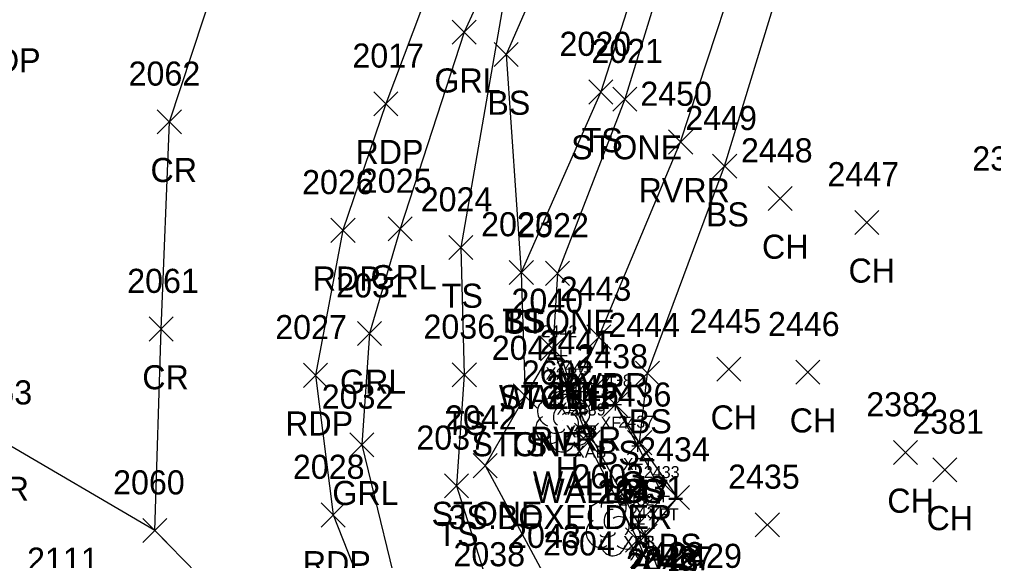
# Model space of a CAD drawing. Extents: x 1459992 to 1461532, y 647785 to 648535.
# Drawn here: x 1461256.6 to 1461337.5, y 648237.3 to 648282.2 of the extents above; entities that cross this region are included whole.
import ezdxf

# ---------------------------------------------------------------- set-up
doc = ezdxf.new("R2010")
doc.units = 0
for name, color, linetype in [('B_A', 7, 'Continuous'), ('B_I', 7, 'Continuous'), ('B_TIC', 7, 'Continuous'), ('BFT', 7, 'Continuous'), ('BSUBM', 7, 'Continuous'), ('L_A', 7, 'Continuous'), ('L_C', 7, 'Continuous'), ('L_I', 7, 'Continuous'), ('L_TIC', 7, 'Continuous'), ('LASF', 7, 'Continuous'), ('LAWE', 7, 'Continuous'), ('LELB', 7, 'Continuous'), ('LTD', 7, 'Continuous'), ('LW', 7, 'Continuous'), ('P_A', 7, 'Continuous'), ('P_I', 7, 'Continuous'), ('P_TIC', 7, 'Continuous'), ('PET', 7, 'Continuous'), ('PRC', 7, 'Continuous'), ('R_A', 7, 'Continuous'), ('R_I', 7, 'Continuous'), ('R_TIC', 7, 'Continuous'), ('RGR', 7, 'Continuous')]:
    doc.layers.add(name, color=color, linetype=linetype)

msp = doc.modelspace()

# ---------------------------------------------------------------- linework, layer by layer
at = {"layer": 'B_TIC'}
for p, q in [((1461301.592, 648254.329), (1461301.668, 648254.329)), ((1461302.498, 648251.414), (1461302.573, 648251.414)), ((1461306.117, 648250.248), (1461306.193, 648250.248)), ((1461303.233, 648249.536), (1461303.309, 648249.536)), ((1461303.233, 648249.536), (1461303.309, 648249.536)), ((1461303.947, 648247.839), (1461304.022, 648247.839)), ((1461307.973, 648246.826), (1461308.049, 648246.826)), ((1461310.088, 648242.646), (1461310.164, 648242.646)), ((1461308.01, 648240.352), (1461308.085, 648240.352)), ((1461308.01, 648240.352), (1461308.085, 648240.352)), ((1461308.563, 648239.319), (1461308.638, 648239.319))]:
    msp.add_line(p, q, dxfattribs=at)
for points in [[(1461301.589, 648253.829), (1461301.589, 648254.829)], [(1461301.089, 648254.329), (1461302.089, 648254.329)], [(1461301.994, 648251.414), (1461302.994, 648251.414)], [(1461302.494, 648250.914), (1461302.494, 648251.914)], [(1461306.114, 648249.748), (1461306.114, 648250.748)], [(1461303.23, 648249.036), (1461303.23, 648250.036)], [(1461303.23, 648249.036), (1461303.23, 648250.036)], [(1461305.614, 648250.248), (1461306.614, 648250.248)], [(1461302.73, 648249.536), (1461303.73, 648249.536)], [(1461302.73, 648249.536), (1461303.73, 648249.536)], [(1461303.943, 648247.339), (1461303.943, 648248.339)], [(1461303.443, 648247.839), (1461304.443, 648247.839)], [(1461307.47, 648246.826), (1461308.47, 648246.826)], [(1461307.97, 648246.326), (1461307.97, 648247.326)], [(1461309.585, 648242.646), (1461310.585, 648242.646)], [(1461310.085, 648242.146), (1461310.085, 648243.146)], [(1461307.506, 648240.352), (1461308.506, 648240.352)], [(1461307.506, 648240.352), (1461308.506, 648240.352)], [(1461308.006, 648239.852), (1461308.006, 648240.852)], [(1461308.006, 648239.852), (1461308.006, 648240.852)], [(1461308.059, 648239.319), (1461309.059, 648239.319)], [(1461308.559, 648238.819), (1461308.559, 648239.819)]]:
    msp.add_lwpolyline(points, dxfattribs=at)
at = {"layer": 'BFT'}
msp.add_lwpolyline([(1461308.006, 648240.352), (1461310.085, 648242.646), (1461307.97, 648246.826), (1461306.114, 648250.248), (1461303.23, 648249.536)], dxfattribs=at)
at = {"layer": 'BSUBM'}
msp.add_lwpolyline([(1461289.479, 648204.615), (1461290.611, 648203.988), (1461292.337, 648203.444), (1461295.791, 648207.872), (1461298.63, 648210.737), (1461303.235, 648215.695), (1461306.926, 648219.818), (1461308.297, 648222.092), (1461310.762, 648233.32), (1461310.733, 648233.836), (1461308.559, 648239.319), (1461308.006, 648240.352), (1461303.943, 648247.839), (1461303.23, 648249.536), (1461302.494, 648251.414), (1461301.589, 648254.329)], dxfattribs=at)
at = {"layer": 'L_TIC'}
for points in [[(1461296.024, 648278.303), (1461298.024, 648280.303)], [(1461298.024, 648278.303), (1461296.024, 648280.303)], [(1461303.882, 648275.195), (1461305.882, 648277.195)], [(1461305.882, 648275.195), (1461303.882, 648277.195)], [(1461305.874, 648274.606), (1461307.874, 648276.606)], [(1461307.874, 648274.606), (1461305.874, 648276.606)], [(1461310.515, 648271.047), (1461312.515, 648273.047)], [(1461312.515, 648271.047), (1461310.515, 648273.047)], [(1461314.171, 648269.035), (1461316.171, 648271.035)], [(1461316.171, 648269.035), (1461314.171, 648271.035)], [(1461318.786, 648266.354), (1461320.786, 648268.354)], [(1461320.786, 648266.354), (1461318.786, 648268.354)], [(1461325.969, 648264.372), (1461327.969, 648266.372)], [(1461327.969, 648264.372), (1461325.969, 648266.372)], [(1461292.267, 648262.285), (1461294.267, 648264.285)], [(1461294.267, 648262.285), (1461292.267, 648264.285)], [(1461297.284, 648260.218), (1461299.284, 648262.218)], [(1461299.284, 648260.218), (1461297.284, 648262.218)], [(1461297.284, 648260.218), (1461299.284, 648262.218)], [(1461299.284, 648260.218), (1461297.284, 648262.218)], [(1461300.288, 648260.14), (1461302.288, 648262.14)], [(1461302.288, 648260.14), (1461300.288, 648262.14)], [(1461303.732, 648254.86), (1461305.732, 648256.86)], [(1461305.732, 648254.86), (1461303.732, 648256.86)], [(1461299.891, 648253.869), (1461301.891, 648255.869)], [(1461301.891, 648253.869), (1461299.891, 648255.869)], [(1461299.891, 648253.869), (1461301.891, 648255.869)], [(1461301.891, 648253.869), (1461299.891, 648255.869)], [(1461307.77, 648251.863), (1461309.77, 648253.863)], [(1461309.77, 648251.863), (1461307.77, 648253.863)], [(1461314.515, 648252.183), (1461316.515, 648254.183)], [(1461316.515, 648252.183), (1461314.515, 648254.183)], [(1461321.086, 648251.933), (1461323.086, 648253.933)], [(1461323.086, 648251.933), (1461321.086, 648253.933)], [(1461292.552, 648251.72), (1461294.552, 648253.72)], [(1461294.552, 648251.72), (1461292.552, 648253.72)], [(1461301.494, 648250.414), (1461303.494, 648252.414)], [(1461303.494, 648250.414), (1461301.494, 648252.414)], [(1461297.603, 648249.96), (1461299.603, 648251.96)], [(1461299.603, 648249.96), (1461297.603, 648251.96)], [(1461297.603, 648249.96), (1461299.603, 648251.96)], [(1461299.603, 648249.96), (1461297.603, 648251.96)], [(1461305.114, 648249.248), (1461307.114, 648251.248)], [(1461307.114, 648249.248), (1461305.114, 648251.248)], [(1461302.696, 648246.711), (1461304.696, 648248.711)], [(1461304.696, 648246.711), (1461302.696, 648248.711)], [(1461302.821, 648246.088), (1461304.821, 648248.088)], [(1461304.821, 648246.088), (1461302.821, 648248.088)], [(1461307.112, 648246.085), (1461309.112, 648248.085)], [(1461309.112, 648246.085), (1461307.112, 648248.085)], [(1461307.112, 648246.085), (1461309.112, 648248.085)], [(1461309.112, 648246.085), (1461307.112, 648248.085)], [(1461329.192, 648245.273), (1461331.192, 648247.273)], [(1461331.192, 648245.273), (1461329.192, 648247.273)], [(1461294.289, 648244.182), (1461296.289, 648246.182)], [(1461296.289, 648244.182), (1461294.289, 648246.182)], [(1461332.45, 648243.824), (1461334.45, 648245.824)], [(1461334.45, 648243.824), (1461332.45, 648245.824)], [(1461291.905, 648242.507), (1461293.905, 648244.507)], [(1461293.905, 648242.507), (1461291.905, 648244.507)], [(1461310.248, 648241.529), (1461312.248, 648243.529)], [(1461312.248, 648241.529), (1461310.248, 648243.529)], [(1461317.719, 648239.265), (1461319.719, 648241.265)], [(1461319.719, 648239.265), (1461317.719, 648241.265)], [(1461307.559, 648238.319), (1461309.559, 648240.319)], [(1461309.559, 648238.319), (1461307.559, 648240.319)], [(1461306.944, 648238.012), (1461308.944, 648240.012)], [(1461308.944, 648238.012), (1461306.944, 648240.012)]]:
    msp.add_lwpolyline(points, dxfattribs=at)
at = {"layer": 'LASF'}
msp.add_lwpolyline([(1461385.213, 648380.492), (1461366.248, 648363.55), (1461348.098, 648349.519), (1461330.912, 648328.279), (1461323.073, 648320.206), (1461313.493, 648297.123), (1461306.874, 648275.606), (1461301.288, 648261.14), (1461300.891, 648254.869), (1461298.603, 648250.96), (1461295.289, 648245.182), (1461300.607, 648235.351), (1461302.655, 648226.754), (1461299.855, 648225.177), (1461298.501, 648223.598), (1461297.241, 648222.361)], dxfattribs=at)
at = {"layer": 'LAWE'}
msp.add_lwpolyline([(1461302.494, 648251.414), (1461304.732, 648255.86), (1461311.515, 648272.047), (1461318.184, 648292.347), (1461320.876, 648299.253), (1461325.88, 648305.325), (1461332.947, 648314.572), (1461346.563, 648331.413), (1461356.783, 648344.505), (1461369.936, 648357.821), (1461389.241, 648367.573), (1461411.269, 648373.546), (1461437.484, 648371.916), (1461454.448, 648377.931), (1461478.943, 648382.173)], dxfattribs=at)
at = {"layer": 'LELB'}
for points in [[(1461437.888, 648410.488), (1461418.935, 648407.67), (1461409.615, 648403.832), (1461397.123, 648398.784), (1461381.61, 648386.31), (1461361.675, 648369.148), (1461343.966, 648353.542), (1461325.103, 648333.829), (1461318.696, 648322.255), (1461308.654, 648307.17), (1461301.589, 648300.067), (1461298.1, 648291.151), (1461293.267, 648263.285), (1461293.552, 648252.72), (1461292.905, 648243.507), (1461295.985, 648233.828), (1461296.733, 648225.477), (1461296.732, 648222.487)], [(1461409.615, 648403.832), (1461399.481, 648396.087), (1461384.513, 648382.595), (1461363.674, 648367.201), (1461346.459, 648351.009), (1461329.681, 648330.054), (1461321.263, 648319.556), (1461311.802, 648297.779), (1461304.882, 648276.195), (1461298.284, 648261.218), (1461298.603, 648250.96)], [(1461308.559, 648239.319), (1461311.248, 648242.529), (1461308.112, 648247.085), (1461308.77, 648252.863), (1461315.171, 648270.035), (1461321.583, 648291.019), (1461329.024, 648302.011), (1461334.847, 648312.35), (1461349.259, 648326.907), (1461358.54, 648342.564), (1461371.773, 648355.493), (1461390.676, 648365.061), (1461413.445, 648369.696), (1461437.721, 648367.905), (1461455.543, 648374.902), (1461479.25, 648378.908)], [(1461322.757, 648336.157), (1461311.114, 648316.428), (1461308.654, 648307.17), (1461305.395, 648298.419), (1461297.024, 648279.303), (1461298.284, 648261.218)], [(1461308.112, 648247.085), (1461306.114, 648250.248)]]:
    msp.add_lwpolyline(points, dxfattribs=at)
at = {"layer": 'LTD'}
for p, q in [((1461301.713, 648248.911), (1461301.713, 648248.911)), ((1461301.713, 648248.911), (1461301.713, 648248.911)), ((1461305.912, 648240.29), (1461305.912, 648240.29)), ((1461305.912, 648240.29), (1461305.912, 648240.29))]:
    msp.add_line(p, q, dxfattribs=at)
for centre in [(1461301.76, 648250.345), (1461305.959, 648241.724)]:
    msp.add_arc(centre, 1.047, 335.52715, 180.95627, dxfattribs=at)
for centre, major_axis, ratio, start_param, end_param in [((1461300.921, 648249.578), (1.21, -0.512), 0.895232, 1.570796, 4.712389), ((1461302.754, 648249.495), (-1.141, -0.483), 0.949671, 1.570796, 4.712389), ((1461301.504, 648249.37), (-0.208, -0.792), 0.645439, 3.141593, 6.283185), ((1461300.63, 648248.203), (0.584, -1.042), 0.959034, 3.141593, 6.283185), ((1461302.213, 648248.745), (-0.5, 0.667), 0.989748, 3.141593, 6.283185), ((1461302.713, 648248.078), (-1.09, 0.792), 0.841452, 1.570796, 4.712389), ((1461301.255, 648248.161), (-0.625, -0.083), 0.423636, 0, 3.141593), ((1461301.713, 648247.411), (0.265, 1.061), 0.942809, 1.570796, 4.712389), ((1461305.12, 648240.956), (1.21, -0.512), 0.895232, 1.570796, 4.712389), ((1461306.954, 648240.873), (-1.141, -0.483), 0.949671, 1.570796, 4.712389), ((1461305.704, 648240.748), (-0.208, -0.792), 0.645439, 3.141593, 6.283185), ((1461306.412, 648240.123), (-0.5, 0.667), 0.989748, 3.141593, 6.283185), ((1461304.829, 648239.581), (0.584, -1.042), 0.959034, 3.141593, 6.283185), ((1461306.912, 648239.457), (-1.09, 0.792), 0.841452, 1.570796, 4.712389), ((1461305.454, 648239.54), (-0.625, -0.083), 0.423636, 0, 3.141593), ((1461305.912, 648238.79), (0.265, 1.061), 0.942809, 1.570796, 4.712389)]:
    msp.add_ellipse(centre, major_axis=major_axis, ratio=ratio, start_param=start_param, end_param=end_param, dxfattribs=at)
at = {"layer": 'LW'}
msp.add_lwpolyline([(1461300.891, 648254.869), (1461303.696, 648247.711), (1461303.821, 648247.088), (1461307.944, 648239.012), (1461310.39, 648233.285), (1461310.304, 648232.944), (1461307.869, 648222.565), (1461307.689, 648222.448), (1461306.595, 648221.184)], dxfattribs=at)
at = {"layer": 'P_TIC'}
for points in [[(1461286.028, 648274.217), (1461288.028, 648276.217)], [(1461288.028, 648274.217), (1461286.028, 648276.217)], [(1461268.056, 648272.722), (1461270.056, 648274.722)], [(1461270.056, 648272.722), (1461268.056, 648274.722)], [(1461282.474, 648263.713), (1461284.474, 648265.713)], [(1461284.474, 648263.713), (1461282.474, 648265.713)], [(1461267.374, 648255.519), (1461269.374, 648257.519)], [(1461269.374, 648255.519), (1461267.374, 648257.519)], [(1461280.187, 648251.679), (1461282.187, 648253.679)], [(1461282.187, 648251.679), (1461280.187, 648253.679)], [(1461281.653, 648240.085), (1461283.653, 648242.085)], [(1461283.653, 648240.085), (1461281.653, 648242.085)], [(1461266.854, 648238.793), (1461268.854, 648240.793)], [(1461268.854, 648238.793), (1461266.854, 648240.793)], [(1461266.854, 648238.793), (1461268.854, 648240.793)], [(1461268.854, 648238.793), (1461266.854, 648240.793)]]:
    msp.add_lwpolyline(points, dxfattribs=at)
at = {"layer": 'PET'}
msp.add_lwpolyline([(1461306.541, 648318.18), (1461294.48, 648294.993), (1461287.028, 648275.217), (1461283.474, 648264.713), (1461281.187, 648252.679), (1461282.653, 648241.085), (1461286.238, 648232.059), (1461291.364, 648224.94), (1461295.532, 648221.126), (1461291.541, 648216.46), (1461287.609, 648211.808)], dxfattribs=at)
at = {"layer": 'PRC'}
for points in [[(1461291.541, 648216.46), (1461279.758, 648227.625), (1461267.854, 648239.793), (1461268.374, 648256.519), (1461269.056, 648273.722), (1461275.705, 648293.856)], [(1461267.854, 648239.793), (1461255.099, 648247.261), (1461235.484, 648257.265), (1461213.087, 648269.852)]]:
    msp.add_lwpolyline(points, dxfattribs=at)
at = {"layer": 'R_TIC'}
for points in [[(1461292.529, 648280.151), (1461294.529, 648282.151)], [(1461294.529, 648280.151), (1461292.529, 648282.151)], [(1461287.214, 648263.827), (1461289.214, 648265.827)], [(1461289.214, 648263.827), (1461287.214, 648265.827)], [(1461284.682, 648255.142), (1461286.682, 648257.142)], [(1461286.682, 648255.142), (1461284.682, 648257.142)], [(1461284.047, 648245.912), (1461286.047, 648247.912)], [(1461286.047, 648245.912), (1461284.047, 648247.912)]]:
    msp.add_lwpolyline(points, dxfattribs=at)
at = {"layer": 'RGR'}
msp.add_lwpolyline([(1461308.996, 648299.797), (1461305.395, 648298.419), (1461298.1, 648291.151), (1461293.529, 648281.151), (1461288.214, 648264.827), (1461285.682, 648256.142), (1461285.047, 648246.912), (1461288.678, 648232.012), (1461291.542, 648226.044), (1461295.805, 648221.25)], dxfattribs=at)

# ---------------------------------------------------------------- texts
at = {"layer": 'B_A'}
for s, p in [('XAB', (1461300.309, 648252.329)), ('XAB', (1461301.215, 648249.414)), ('XFT', (1461304.858, 648248.248)), ('XAB', (1461301.95, 648247.536)), ('XFT', (1461301.974, 648247.536)), ('XAB', (1461302.664, 648245.839)), ('XFT', (1461306.714, 648244.826)), ('XFT', (1461308.829, 648240.646)), ('XAB', (1461306.727, 648238.352)), ('XFT', (1461306.75, 648238.352)), ('XAB', (1461307.28, 648237.319))]:
    msp.add_text(s, height=1, dxfattribs=at).set_placement(p)
at = {"layer": 'B_I'}
for s, p in [('2442', (1461299.959, 648255.829)), ('2441', (1461301.148, 648252.914)), ('2438', (1461304.484, 648251.748)), ('2440', (1461301.556, 648251.036)), ('2440', (1461301.556, 648251.036)), ('2439', (1461302.309, 648249.339)), ('2437', (1461306.34, 648248.326)), ('2433', (1461308.455, 648244.146)), ('2432', (1461306.376, 648241.852)), ('2432', (1461306.376, 648241.852)), ('2431', (1461307.213, 648240.819))]:
    msp.add_text(s, height=1, dxfattribs=at).set_placement(p)
at = {"layer": 'L_A'}
for s, p in [('BS', (1461295.465, 648274.303)), ('STONE', (1461302.418, 648270.606)), ('TS', (1461303.291, 648271.195)), ('RVRR', (1461308.027, 648267.047)), ('BS', (1461313.612, 648265.035)), ('CH', (1461318.274, 648262.354)), ('CH', (1461325.458, 648260.372)), ('TS', (1461291.677, 648258.285)), ('TS', (1461296.693, 648256.218)), ('BS', (1461296.725, 648256.218)), ('STONE', (1461296.831, 648256.14)), ('RVRR', (1461301.244, 648250.86)), ('WALLC', (1461296.426, 648249.869)), ('STONE', (1461296.434, 648249.869)), ('BS', (1461307.211, 648247.863)), ('CH', (1461314.003, 648248.183)), ('CH', (1461320.574, 648247.933)), ('TS', (1461291.961, 648247.72)), ('RVRR', (1461299.006, 648246.414)), ('STONE', (1461294.146, 648245.96)), ('TS', (1461297.012, 648245.96)), ('BS', (1461304.555, 648245.248)), ('H', (1461301.146, 648243.911)), ('WALLC', (1461299.232, 648242.711)), ('WALLC', (1461299.357, 648242.088)), ('BS', (1461306.553, 648242.085)), ('BS', (1461306.553, 648242.085)), ('CH', (1461328.68, 648241.273)), ('STONE', (1461290.832, 648240.182)), ('CH', (1461331.938, 648239.824)), ('TS', (1461291.314, 648238.507)), ('BS', (1461309.689, 648237.529))]:
    msp.add_text(s, height=2, dxfattribs=at).set_placement(p)
at = {"layer": 'L_C'}
msp.add_text('3S.BOXELDER', height=2, dxfattribs=at).set_placement((1461292.24, 648239.911))
at = {"layer": 'L_I'}
for s, p in [('2020', (1461301.456, 648279.195)), ('2021', (1461304.103, 648278.606)), ('2450', (1461308.168, 648275.047)), ('2449', (1461311.904, 648273.035)), ('2448', (1461316.526, 648270.354)), ('2389', (1461335.736, 648269.677)), ('2447', (1461323.709, 648268.372)), ('2024', (1461289.929, 648266.285)), ('2023', (1461294.945, 648264.218)), ('2023', (1461294.945, 648264.218)), ('2022', (1461297.949, 648264.14)), ('2443', (1461301.472, 648258.86)), ('2040', (1461297.465, 648257.869)), ('2040', (1461297.465, 648257.869)), ('2444', (1461305.51, 648255.863)), ('2445', (1461312.255, 648256.183)), ('2446', (1461318.771, 648255.933)), ('2036', (1461290.158, 648255.72)), ('2441', (1461299.801, 648254.414)), ('2041', (1461295.831, 648253.96)), ('2041', (1461295.831, 648253.96)), ('2438', (1461302.854, 648253.248)), ('2602', (1461298.327, 648251.911)), ('2045', (1461300.358, 648250.711)), ('2046', (1461300.428, 648250.088)), ('2436', (1461304.797, 648250.085)), ('2436', (1461304.797, 648250.085)), ('2382', (1461326.932, 648249.273)), ('2042', (1461291.951, 648248.182)), ('2381', (1461330.757, 648247.824)), ('2037', (1461289.566, 648246.507)), ('2434', (1461307.988, 648245.529)), ('2603', (1461302.526, 648243.29)), ('2435', (1461315.459, 648243.265)), ('2431', (1461305.866, 648242.319)), ('2047', (1461304.605, 648242.012)), ('2043', (1461297.269, 648238.351)), ('2604', (1461300.101, 648237.725)), ('2038', (1461292.647, 648236.828)), ('2428', (1461307.474, 648236.836)), ('2427', (1461308.284, 648236.492)), ('2429', (1461310.658, 648236.696)), ('2049', (1461306.957, 648235.944)), ('2048', (1461307.052, 648236.285))]:
    msp.add_text(s, height=2, dxfattribs=at).set_placement(p)
at = {"layer": 'P_A'}
for s, p in [('RDP', (1461252.718, 648277.826)), ('RDP', (1461284.516, 648270.217)), ('CR', (1461267.489, 648268.722)), ('RDP', (1461280.962, 648259.713)), ('CR', (1461266.807, 648251.519)), ('RDP', (1461278.675, 648247.679)), ('CR', (1461253.532, 648242.261)), ('CR', (1461253.532, 648242.261)), ('RDP', (1461280.141, 648236.085))]:
    msp.add_text(s, height=2, dxfattribs=at).set_placement(p)
at = {"layer": 'P_I'}
for s, p in [('2017', (1461284.256, 648278.217)), ('2062', (1461265.67, 648276.722)), ('2026', (1461280.08, 648267.713)), ('2061', (1461265.555, 648259.519)), ('2027', (1461277.848, 648255.679)), ('2063', (1461251.713, 648250.261)), ('2063', (1461251.713, 648250.261)), ('2028', (1461279.314, 648244.085)), ('2060', (1461264.382, 648242.793)), ('2060', (1461264.382, 648242.793)), ('2111', (1461257.24, 648236.378))]:
    msp.add_text(s, height=2, dxfattribs=at).set_placement(p)
at = {"layer": 'R_A'}
for p in [(1461291.072, 648276.151), (1461285.758, 648259.827), (1461283.226, 648251.142), (1461282.591, 648241.912)]:
    msp.add_text('GRL', height=2, dxfattribs=at).set_placement(p)
at = {"layer": 'R_I'}
for s, p in [('2025', (1461284.876, 648267.827)), ('2031', (1461282.911, 648259.142)), ('2032', (1461281.709, 648249.912))]:
    msp.add_text(s, height=2, dxfattribs=at).set_placement(p)

doc.saveas('drawing.dxf')
